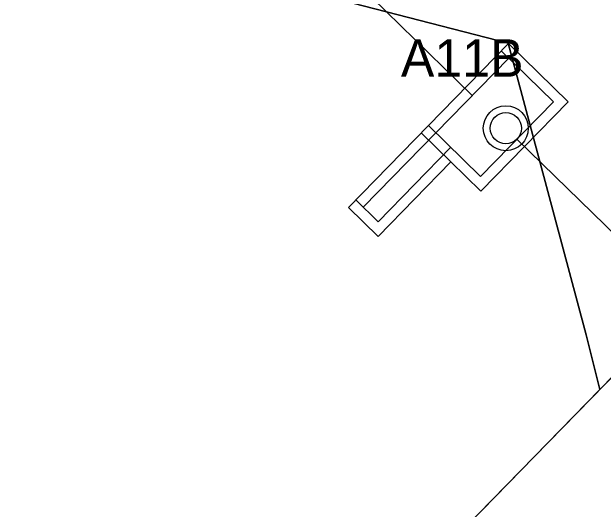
# Model space of a CAD drawing. Extents: x 2252703 to 2264864, y 13787568 to 13790989.
# Drawn here: x 2253433.6 to 2253462, y 13789220.88 to 13789244.76 of the extents above; entities that cross this region are included whole.
import ezdxf

# ---------------------------------------------------------------- set-up
doc = ezdxf.new("R2010")
doc.units = 0
for name, color, linetype in [('D_DRAIN_MISC', 7, 'Continuous'), ('D_DRAIN_NOTES_1', 7, 'Continuous'), ('D_DRN_AREA_X', 7, 'Continuous'), ('D_INLET_1', 7, 'Continuous'), ('D_PIPES_1', 7, 'Continuous')]:
    doc.layers.add(name, color=color, linetype=linetype)

msp = doc.modelspace()

# ---------------------------------------------------------------- linework, layer by layer
at = {"layer": 'D_DRAIN_MISC'}
for p, q in [((2253458.537, 13789241.483), (2253458.537, 13789241.483)), ((2253455.717, 13789240.744), (2253455.717, 13789240.744)), ((2253456.789, 13789239.695), (2253456.789, 13789239.695)), ((2253457.862, 13789238.647), (2253457.862, 13789238.647)), ((2253455.042, 13789237.907), (2253455.042, 13789237.907))]:
    msp.add_line(p, q, dxfattribs=at)
at = {"layer": 'D_DRN_AREA_X'}
for p, q in [((2253422.582, 13789252.265), (2253457.441, 13789243.253)), ((2253457.441, 13789243.253), (2253422.582, 13789252.265)), ((2253457.441, 13789243.253), (2253461.185, 13789229.256)), ((2253461.185, 13789229.256), (2253457.441, 13789243.253)), ((2253461.185, 13789229.256), (2253461.84, 13789226.622)), ((2253461.84, 13789226.622), (2253461.185, 13789229.256)), ((2253330.48, 13789092.206), (2253461.84, 13789226.622))]:
    msp.add_line(p, q, dxfattribs=at)
for points in [[(2253461.84, 13789226.622), (2253498.787, 13789264.428), (2253510.627, 13789276.543), (2253522.309, 13789288.497), (2253549.932, 13789316.763), (2253586.446, 13789354.127), (2253603.904, 13789371.991)], [(2253498.787, 13789264.428), (2253238.605, 13788998.193), (2253219.877, 13788979.029)]]:
    msp.add_lwpolyline(points, dxfattribs=at)
at = {"layer": 'D_INLET_1'}
for p, q in [((2253457.456, 13789243.239), (2253449.768, 13789235.372)), ((2253460.317, 13789240.443), (2253457.456, 13789243.239)), ((2253459.609, 13789240.435), (2253457.106, 13789242.881)), ((2253457.464, 13789242.532), (2253450.475, 13789235.38)), ((2253459.609, 13789240.435), (2253456.115, 13789236.859)), ((2253460.317, 13789240.443), (2253456.123, 13789236.152)), ((2253456.115, 13789236.859), (2253453.612, 13789239.305)), ((2253454.693, 13789237.55), (2253453.262, 13789238.948)), ((2253454.684, 13789238.257), (2253451.19, 13789234.681)), ((2253454.693, 13789237.55), (2253451.198, 13789233.974)), ((2253456.123, 13789236.152), (2253454.693, 13789237.55)), ((2253451.19, 13789234.681), (2253450.117, 13789235.729)), ((2253451.198, 13789233.974), (2253449.768, 13789235.372))]:
    msp.add_line(p, q, dxfattribs=at)
for radius in [1.08, 0.75]:
    msp.add_circle((2253457.326, 13789239.171), radius, dxfattribs=at)
at = {"layer": 'D_PIPES_1'}
for p, q in [((2253455.717, 13789240.744), (2253428.003, 13789267.827)), ((2253470.914, 13789225.892), (2253457.862, 13789238.647))]:
    msp.add_line(p, q, dxfattribs=at)

# ---------------------------------------------------------------- texts
at = {"layer": 'D_DRAIN_NOTES_1'}
msp.add_text('A11B', height=1.8, dxfattribs=at).set_placement((2253452.288, 13789241.644))

doc.saveas('drawing.dxf')
